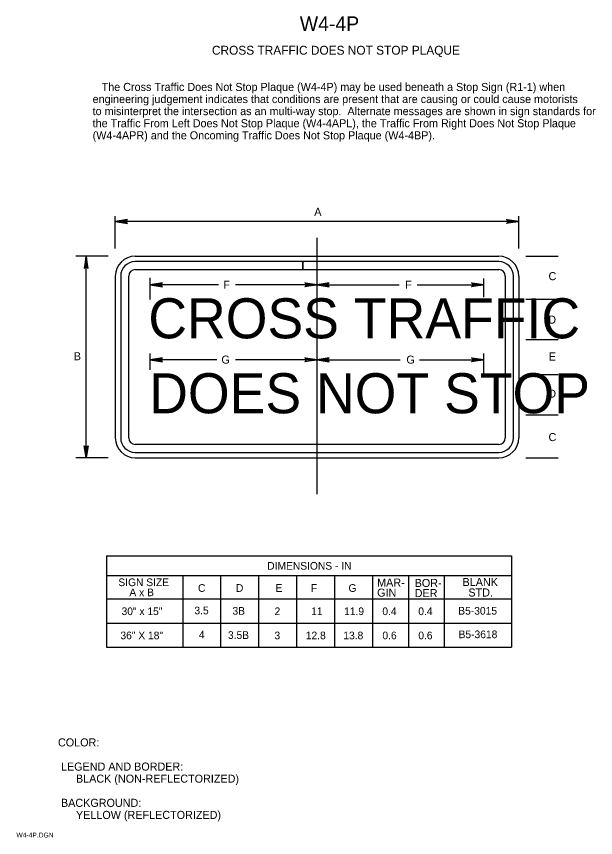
# Model space of a CAD drawing. Extents: x 0.013 to 0.192, y 0.004 to 0.259.
import ezdxf

# ---------------------------------------------------------------- set-up
doc = ezdxf.new("R2010")
doc.units = 0
for name, color, linetype in [('1', 7, 'Continuous'), ('2', 7, 'Continuous'), ('3', 7, 'Continuous')]:
    doc.layers.add(name, color=color, linetype=linetype)

# ---------------------------------------------------------------- blocks, each defined once
blk = doc.blocks.new('RARROW')
at = {"layer": '3'}
for p, q in [((-2.156, 0.285), (-2.2665, 0.384625)), ((-2.2665, 0.384625), (0, 0)), ((0, 0), (-2.2665, -0.379125)), ((-2.156, 0.285), (-2.075625, 0.12075)), ((0, 0), (-2.156, 0.285)), ((-2.14975, -0.2705), (0, 0)), ((-2.075625, 0.12075), (0, 0)), ((0, 0), (-2.074, -0.108)), ((-2.2665, -0.379125), (-2.14975, -0.2705)), ((-2.074, -0.108), (-2.14975, -0.2705))]:
    blk.add_line(p, q, dxfattribs=at)

msp = doc.modelspace()

# ---------------------------------------------------------------- linework, layer by layer
at = {"layer": '1'}
for p, q in [((0.10565, 0.11086), (0.10565, 0.19039)), ((0.0341, 0.12213), (0.0341, 0.18463)), ((0.10127, 0.18297), (0.04931, 0.18297)), ((0.10127, 0.18047), (0.10127, 0.18297)), ((0.16198, 0.18297), (0.10127, 0.18297)), ((0.10127, 0.18297), (0.10127, 0.18047)), ((0.04481, 0.17847), (0.04481, 0.1283)), ((0.04731, 0.1283), (0.04731, 0.17847)), ((0.04931, 0.18047), (0.10127, 0.18047)), ((0.10127, 0.18047), (0.16198, 0.18047)), ((0.16398, 0.17847), (0.16398, 0.1283)), ((0.16648, 0.1283), (0.16648, 0.17847)), ((0.05398, 0.17123), (0.05398, 0.17793)), ((0.10565, 0.17326), (0.10565, 0.17793)), ((0.15731, 0.17194), (0.15731, 0.17769)), ((0.05398, 0.14943), (0.05398, 0.15446)), ((0.10565, 0.15098), (0.10565, 0.1541)), ((0.15731, 0.14823), (0.15731, 0.15446)), ((0.16198, 0.1263), (0.04931, 0.1263)), ((0.04931, 0.1238), (0.16198, 0.1238))]:
    msp.add_line(p, q, dxfattribs=at)
for centre, radius, start, end in [((0.04931, 0.17847), 0.00617, 90, 180), ((0.16198, 0.17847), 0.00617, 360, 90), ((0.04931, 0.17847), 0.0045, 90, 180), ((0.16198, 0.17847), 0.0045, 0, 90), ((0.04931, 0.17847), 0.002, 90, 180), ((0.16198, 0.17847), 0.002, 0, 90), ((0.04931, 0.1283), 0.00617, 180, 270), ((0.04931, 0.1283), 0.0045, 180, 270), ((0.04931, 0.1283), 0.002, 180, 270), ((0.16198, 0.1283), 0.00617, 270, 0), ((0.16198, 0.1283), 0.0045, 270, 0), ((0.16198, 0.1283), 0.002, 270, 0)]:
    msp.add_arc(centre, radius, start, end, dxfattribs=at)
at = {"layer": '3'}
for p, q in [((0.04315, 0.18704), (0.04315, 0.1971)), ((0.16815, 0.18704), (0.16815, 0.1971)), ((0.16815, 0.19541), (0.04315, 0.19541)), ((0.04098, 0.18463), (0.03092, 0.18463)), ((0.04931, 0.18463), (0.16198, 0.18463)), ((0.17031, 0.18463), (0.18037, 0.18463)), ((0.04315, 0.17847), (0.04315, 0.1283)), ((0.16815, 0.17847), (0.16815, 0.1283)), ((0.07509, 0.17577), (0.05398, 0.17577)), ((0.10565, 0.17577), (0.08036, 0.17577)), ((0.10565, 0.17577), (0.13114, 0.17577)), ((0.13665, 0.17577), (0.15731, 0.17577)), ((0.17031, 0.1713), (0.18037, 0.1713)), ((0.17031, 0.1588), (0.18037, 0.1588)), ((0.07461, 0.15254), (0.05398, 0.15254)), ((0.10565, 0.15254), (0.08036, 0.15254)), ((0.10565, 0.15254), (0.13138, 0.15254)), ((0.13737, 0.15254), (0.15731, 0.15254)), ((0.17031, 0.14796), (0.18037, 0.14796)), ((0.17031, 0.13546), (0.18037, 0.13546)), ((0.04098, 0.12213), (0.03092, 0.12213)), ((0.04931, 0.12213), (0.16198, 0.12213)), ((0.17031, 0.12213), (0.18037, 0.12213)), ((0.04046, 0.09173), (0.16589, 0.09173)), ((0.04046, 0.09168), (0.04046, 0.06336)), ((0.16589, 0.09173), (0.16589, 0.06336)), ((0.16589, 0.08548), (0.04046, 0.08548)), ((0.06402, 0.08548), (0.06402, 0.06336)), ((0.07577, 0.08543), (0.07577, 0.06336)), ((0.08752, 0.08543), (0.08752, 0.06336)), ((0.09927, 0.08543), (0.09927, 0.06336)), ((0.11102, 0.08543), (0.11102, 0.06336)), ((0.12284, 0.08548), (0.12284, 0.06336)), ((0.13396, 0.08548), (0.13396, 0.06336)), ((0.14509, 0.08548), (0.14509, 0.06336)), ((0.04046, 0.07836), (0.16589, 0.07836)), ((0.04046, 0.07086), (0.16589, 0.07086)), ((0.04046, 0.06336), (0.16589, 0.06336))]:
    msp.add_line(p, q, dxfattribs=at)

# ---------------------------------------------------------------- block references
at = {"layer": '3', "xscale": 0.0016545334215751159}
for p, yscale, rotation in [((0.04315, 0.19541), -0.0016366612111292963, -180), ((0.0341, 0.18463), -0.0016366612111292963, 90), ((0.05398, 0.17577), -0.0016366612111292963, -180), ((0.10565, 0.17577), -0.0016366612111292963, -180), ((0.05398, 0.15254), -0.0016366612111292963, -180), ((0.10565, 0.15254), -0.0016366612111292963, -180), ((0.0341, 0.12213), 0.0016366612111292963, -90)]:
    msp.add_blockref('RARROW', p, dxfattribs=dict(at, yscale=yscale, rotation=rotation))
at = {"layer": '3', "xscale": 0.0016545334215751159, "yscale": 0.0016366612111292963}
for p in [(0.16815, 0.19541), (0.10565, 0.17577), (0.15731, 0.17577), (0.10565, 0.15254), (0.15731, 0.15254)]:
    msp.add_blockref('RARROW', p, dxfattribs=at)

# ---------------------------------------------------------------- texts
at = {"layer": '1'}
for s, height, p in [('W4-4P', 0.0045, (0.10031, 0.2545)), ('CROSS TRAFFIC DOES NOT STOP PLAQUE', 0.0027503, (0.07309, 0.24713)), ('COLOR:', 0.0025, (0.02538, 0.03262)), (' LEGEND AND BORDER:', 0.0024998, (0.02538, 0.02512)), ('      BLACK (NON-REFLECTORIZED)', 0.0024998, (0.02538, 0.02138)), (' BACKGROUND:', 0.0024998, (0.02538, 0.01388)), ('      YELLOW (REFLECTORIZED)', 0.0024998, (0.02538, 0.01013)), ('W4-4P.DGN', 0.0015, (0.0125, 0.00438))]:
    msp.add_text(s, height=height, dxfattribs=at).set_placement(p)
at = {"layer": '2'}
for s, height, p in [('   The Cross Traffic Does Not Stop Plaque (W4-4P) may be used beneath a Stop Sign (R1-1) when', 0.0024998, (0.03612, 0.23588)), ('engineering judgement indicates that conditions are present that are causing or could cause motorists', 0.00249975, (0.03612, 0.23213)), ('to misinterpret the intersection as an multi-way stop.  Alternate messages are shown in sign standards for', 0.00249975, (0.03612, 0.22838)), ('the Traffic From Left Does Not Stop Plaque (W4-4APL), the Traffic From Right Does Not Stop Plaque ', 0.0024998, (0.03612, 0.22463)), ('(W4-4APR) and the Oncoming Traffic Does Not Stop Plaque (W4-4BP).', 0.0024998, (0.03612, 0.22088))]:
    msp.add_text(s, height=height, dxfattribs=at).set_placement(p)
at = {"layer": '3'}
for s, height, p in [('A', 0.0025, (0.10479, 0.19716)), ('C', 0.0025, (0.17738, 0.1772)), ('F', 0.0025, (0.13297, 0.17456)), ('CROSS TRAFFIC', 0.01242, (0.05338, 0.15917)), ('B', 0.0025, (0.03028, 0.15237)), ('G', 0.0025, (0.13334, 0.15132)), ('DOES NOT STOP', 0.01242, (0.05365, 0.13593)), ('DIMENSIONS - IN', 0.0023752, (0.09022, 0.08743)), ('SIGN SIZE', 0.002375, (0.04409, 0.08233)), ('MAR-', 0.0025, (0.12427, 0.08218)), ('BOR-', 0.0025, (0.1359, 0.08206)), ('BLANK', 0.0025, (0.15074, 0.08236)), ('A x B', 0.002375, (0.04751, 0.07921)), ('C', 0.00238, (0.06877, 0.08056)), ('D', 0.00238, (0.08052, 0.08056)), ('E', 0.00238, (0.09277, 0.08056)), ('F', 0.00238, (0.10377, 0.08056)), ('G', 0.00238, (0.1154, 0.08056)), ('GIN', 0.0025, (0.12427, 0.07906)), ('STD.', 0.0025, (0.15254, 0.07911)), ('DER', 0.0025, (0.1359, 0.07893)), ('30" x 15"', 0.002375, (0.04508, 0.07335)), ('3.5', 0.002375, (0.06766, 0.07359)), ('3B', 0.002375, (0.07945, 0.07346)), ('2', 0.00238, (0.09248, 0.07334)), ('11', 0.002375, (0.10384, 0.07335)), ('11.9', 0.002375, (0.11403, 0.07335)), ('0.4', 0.002375, (0.12589, 0.07335)), ('0.4', 0.002375, (0.13702, 0.07335)), ('B5-3015', 0.002375, (0.14941, 0.07349)), ('36" X 18"', 0.002375, (0.04473, 0.06585)), ('4', 0.00238, (0.06905, 0.06609)), ('3.5B', 0.002375, (0.07805, 0.06596)), ('3', 0.00238, (0.09247, 0.06584)), ('12.8', 0.002375, (0.10217, 0.06585)), ('13.8', 0.002375, (0.1138, 0.06585)), ('0.6', 0.002375, (0.12591, 0.06585)), ('0.6', 0.002375, (0.13703, 0.06585)), ('B5-3618', 0.002375, (0.14951, 0.06619))]:
    msp.add_text(s, height=height, dxfattribs=at).set_placement(p)
for s, p in [('F', (0.07661, 0.17456)), ('D', (0.1773, 0.16372)), ('G', (0.07602, 0.15132)), ('E', (0.17744, 0.15228)), ('D', (0.1773, 0.14078)), ('C', (0.17738, 0.1273))]:
    msp.add_text(s, height=0.0025, rotation=360, dxfattribs=at).set_placement(p)

doc.saveas('drawing.dxf')
